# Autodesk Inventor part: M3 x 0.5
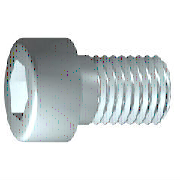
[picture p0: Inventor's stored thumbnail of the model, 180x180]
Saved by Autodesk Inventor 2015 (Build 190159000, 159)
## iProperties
IsCustomPart: 0
Created: 2015-10
Part Number: M3 x 0.5
Material: 강, 연강
Description: 6각머리 태핑 나사
Document SubType Name: Modeling
Standard: KS B 1003
Designer: mdu
Standards Organization: KS
Language: ko-KR
Size Designation: M 3 x 12
Categories: <MemberInstance><Categories><Category DisplayName="조임쇠" InternalName="e4da775c-781d-43d5-af7c-5136215cf5a6" Mnemonic="FSTN"><Category DisplayName="볼트" InternalN
Density: 1 g/cm^3
Appearance: 강철
Author: mdu
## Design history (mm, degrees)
sketch "스케치1"
  geometry: L1 (-0.867, 0)-(12, 0); L2 (12, 0)-(12, 1.5); L3 (12, 1.5)-(1.25, 1.5); L4 (1.25, 1.5)-(0.943, 1.5); L5 (0.943, 1.5)-(0, 1.5); L6 (0, 1.5)-(0, 2.75); L7 (0, 2.75)-(-3, 2.75); L8 (-3, 2.75)-(-3, 1.443); L9 (-3, 1.443)-(-1.7, 1.443); L10 (-1.7, 1.443)-(-0.867, 0); L11 (-6, 0)-(15, 0) reference; L12 (0, -0.55)-(0, 3.3) reference; L13 (1.25, 1.5)-(0, 1.5)
  constraints: 22 end point, 6 parallel, 2 collinear, 2 perpendicular, 1 horizontal, 1 point on line
  dimensions: "d1" = 10.75 distance from line of L3.end L2 (= GEL); "d2" = 0.30683 distance of L4.end L3.end (computed from GAL); "d3" = 3 distance between parallel lines of L8 L6 (= KOH); "d4" = 1.3 distance of L8.end L9.end (= INTI); "d5" = 60 deg angle of L10 L1; "d6" = 3 diameter of L3 L1 (= GD); "d7" = 3 diameter of L5 L1 (= BDM); "d8" = 2.88675 diameter of L9 L1 (= 1.1547 x SW); "d9" = 5.5 diameter of L7 L1 (= KOD); "d26" = 12 distance between parallel lines of L12 L2 (= NLG)
revolve "본체" sketch "스케치1" stored, may be unused: angle "d10" = 90 deg
sketch "스케치2"
  geometry: L1 (0, -3.85)-(0, 3.85) reference; L2 (-3.85, 0)-(3.85, 0) reference; L3 (1.443, 0)-(0.722, -1.25); L4 (0.722, -1.25)-(-0.722, -1.25); L5 (-0.722, -1.25)-(-1.443, 0); L6 (-1.443, 0)-(-0.722, 1.25); L7 (-0.722, 1.25)-(0.722, 1.25); L8 (0.722, 1.25)-(1.443, 0); 2 further points
  constraints: 12 end point, 1 coincident, 1 horizontal alignment, 1 point on line, 12 other
extrude "슬롯" join sketch "스케치2" stored distance "d11" = 10; taper "d12" = 0 deg
workplane "Work Plane1"
fillet "Fillet2" dims "d30" = 0.1 (= R)
body "Solid1"
fillet "모깎기1" dims "d17" = 0.3 (= RR)
feature "스레드" dims "d13" = 10.75 (= GEL), "d14" = 0
chamfer "모따기1" distance "d15" = 0.30673 (= -0.5 x SPD + 0.5 x GD); stored, may be unused: second distance "d16" = 0.30673 (= GUL), angle "d27" = 45 deg
other parameters: "GD" = 3 (= NND) [user parameter; used in 2 equation terms], "NLG" = 12 [user parameter; used in 1 equation term], "GEL" = 10.75 [user parameter; used in 2 equation terms], "KOD" = 5.5 [user parameter; used in 1 equation term], "KOH" = 3 [user parameter; used in 1 equation term], "INTI" = 1.3 [user parameter; used in 1 equation term], "GAL" = 0.30673 (= 0.61345 x PTC) [user parameter; used in 1 equation term], "GUL" = 0.30673 (= 0.61345 x PTC) [user parameter; used in 1 equation term], "BDM" = 3 (= NND) [user parameter; used in 1 equation term], "SW" = 2.5 [user parameter; used in 2 equation terms], "RR" = 0.3 [user parameter; used in 1 equation term], "SPD" = 2.38655 (= NND - 1.2269 x PTC) [user parameter; used in 1 equation term], "d19" = 0, "d28" = 0, "d29" = 0, "R" = 0.1 [user parameter; used in 1 equation term], "PHH" = 0.1 [user parameter], "GD1" = 2.38655 (= THREADDIA - 1.2269 x PTC) [user parameter], "THREADDIA" = 3 [user parameter; used in 1 equation term], "FAWI" = 45 deg [user parameter], "PTC" = 0.5 [user parameter; used in 5 equation terms], "NND" = 3 [user parameter; used in 3 equation terms], "TOA" = 30 deg [user parameter], "E0" = 2.8875 (= 1.155 x SW) [user parameter]
